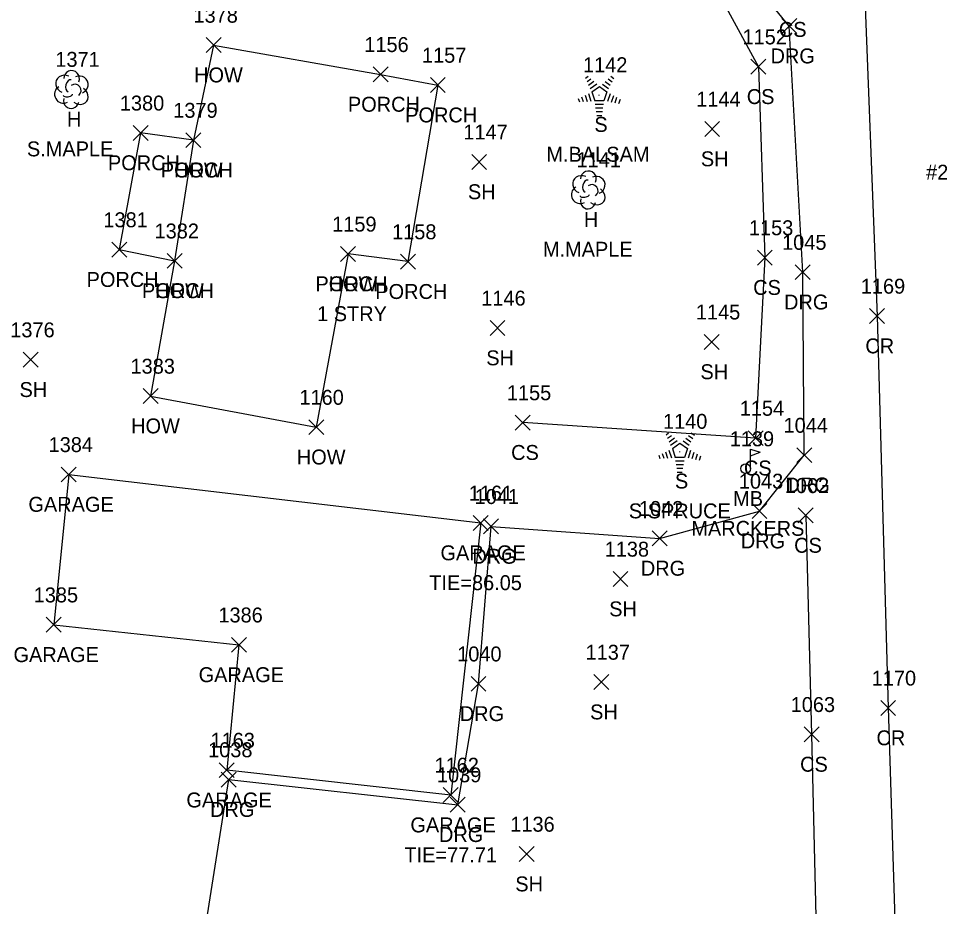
# Model space of a CAD drawing. Extents: x 1609623 to 1616187, y 756677 to 762826.
# Drawn here: x 1610505.6 to 1610629.1, y 761517.1 to 761636.1 of the extents above; entities that cross this region are included whole.
import ezdxf

# ---------------------------------------------------------------- set-up
doc = ezdxf.new("R2010")
doc.units = 0
for name, color, linetype in [('L_A', 7, 'Continuous'), ('L_C', 7, 'Continuous'), ('L_I', 7, 'Continuous'), ('L_TIC', 7, 'Continuous'), ('LBC', 7, 'Continuous'), ('LBF', 7, 'Continuous'), ('LELB', 7, 'Continuous'), ('LMB', 7, 'Continuous'), ('LTC', 7, 'Continuous'), ('LTD', 7, 'Continuous'), ('P_A', 7, 'Continuous'), ('P_I', 7, 'Continuous'), ('P_TIC', 7, 'Continuous'), ('PRC', 7, 'Continuous'), ('R_A', 7, 'Continuous'), ('R_I', 7, 'Continuous'), ('R_TIC', 7, 'Continuous'), ('RDG', 7, 'Continuous'), ('U_C', 7, 'Continuous')]:
    doc.layers.add(name, color=color, linetype=linetype)

msp = doc.modelspace()

# ---------------------------------------------------------------- linework, layer by layer
at = {"layer": 'L_TIC'}
for points in [[(1610530.77, 761631.56), (1610532.77, 761633.56)], [(1610532.77, 761631.56), (1610530.77, 761633.56)], [(1610603.8, 761628.66), (1610605.8, 761630.66)], [(1610605.8, 761628.66), (1610603.8, 761630.66)], [(1610553.15, 761627.63), (1610555.15, 761629.63)], [(1610555.15, 761627.63), (1610553.15, 761629.63)], [(1610560.83, 761626.2), (1610562.83, 761628.2)], [(1610562.83, 761626.2), (1610560.83, 761628.2)], [(1610597.6, 761620.32), (1610599.6, 761622.32)], [(1610599.6, 761620.32), (1610597.6, 761622.32)], [(1610520.98, 761619.79), (1610522.98, 761621.79)], [(1610522.98, 761619.79), (1610520.98, 761621.79)], [(1610528.06, 761618.82), (1610530.06, 761620.82)], [(1610530.06, 761618.82), (1610528.06, 761620.82)], [(1610528.06, 761618.82), (1610530.06, 761620.82)], [(1610530.06, 761618.82), (1610528.06, 761620.82)], [(1610566.37, 761615.91), (1610568.37, 761617.91)], [(1610568.37, 761615.91), (1610566.37, 761617.91)], [(1610518.12, 761604.15), (1610520.12, 761606.15)], [(1610520.12, 761604.15), (1610518.12, 761606.15)], [(1610548.79, 761603.57), (1610550.79, 761605.57)], [(1610550.79, 761603.57), (1610548.79, 761605.57)], [(1610548.79, 761603.57), (1610550.79, 761605.57)], [(1610550.79, 761603.57), (1610548.79, 761605.57)], [(1610604.66, 761603.08), (1610606.66, 761605.08)], [(1610606.66, 761603.08), (1610604.66, 761605.08)], [(1610525.54, 761602.65), (1610527.54, 761604.65)], [(1610527.54, 761602.65), (1610525.54, 761604.65)], [(1610525.54, 761602.65), (1610527.54, 761604.65)], [(1610527.54, 761602.65), (1610525.54, 761604.65)], [(1610556.82, 761602.54), (1610558.82, 761604.54)], [(1610558.82, 761602.54), (1610556.82, 761604.54)], [(1610568.83, 761593.65), (1610570.83, 761595.65)], [(1610570.83, 761593.65), (1610568.83, 761595.65)], [(1610597.54, 761591.79), (1610599.54, 761593.79)], [(1610599.54, 761591.79), (1610597.54, 761593.79)], [(1610506.26, 761589.4), (1610508.26, 761591.4)], [(1610508.26, 761589.4), (1610506.26, 761591.4)], [(1610522.32, 761584.53), (1610524.32, 761586.53)], [(1610524.32, 761584.53), (1610522.32, 761586.53)], [(1610572.21, 761580.97), (1610574.21, 761582.97)], [(1610574.21, 761580.97), (1610572.21, 761582.97)], [(1610544.53, 761580.36), (1610546.53, 761582.36)], [(1610546.53, 761580.36), (1610544.53, 761582.36)], [(1610603.42, 761578.89), (1610605.42, 761580.89)], [(1610605.42, 761578.89), (1610603.42, 761580.89)], [(1610511.34, 761574.02), (1610513.34, 761576.02)], [(1610513.34, 761574.02), (1610511.34, 761576.02)], [(1610610.15, 761568.53), (1610612.15, 761570.53)], [(1610612.15, 761568.53), (1610610.15, 761570.53)], [(1610566.58, 761567.52), (1610568.58, 761569.52)], [(1610568.58, 761567.52), (1610566.58, 761569.52)], [(1610585.31, 761560.01), (1610587.31, 761562.01)], [(1610587.31, 761560.01), (1610585.31, 761562.01)], [(1610509.34, 761553.88), (1610511.34, 761555.88)], [(1610511.34, 761553.88), (1610509.34, 761555.88)], [(1610534.16, 761551.19), (1610536.16, 761553.19)], [(1610536.16, 761551.19), (1610534.16, 761553.19)], [(1610582.75, 761546.2), (1610584.75, 761548.2)], [(1610584.75, 761546.2), (1610582.75, 761548.2)], [(1610610.94, 761539.19), (1610612.94, 761541.19)], [(1610612.94, 761539.19), (1610610.94, 761541.19)], [(1610532.52, 761534.4), (1610534.52, 761536.4)], [(1610534.52, 761534.4), (1610532.52, 761536.4)], [(1610562.55, 761531.06), (1610564.55, 761533.06)], [(1610564.55, 761531.06), (1610562.55, 761533.06)], [(1610572.72, 761523.15), (1610574.72, 761525.15)], [(1610574.72, 761523.15), (1610572.72, 761525.15)]]:
    msp.add_lwpolyline(points, dxfattribs=at)
at = {"layer": 'LBC'}
for points in [[(1610531.77, 761632.56), (1610529.06, 761619.82), (1610526.54, 761603.65), (1610523.32, 761585.53)], [(1610531.77, 761632.56), (1610554.15, 761628.63)], [(1610549.79, 761604.57), (1610545.53, 761581.36)], [(1610523.32, 761585.53), (1610545.53, 761581.36)], [(1610512.34, 761575.02), (1610510.34, 761554.88), (1610535.16, 761552.19)], [(1610512.34, 761575.02), (1610567.58, 761568.52)], [(1610567.58, 761568.52), (1610563.55, 761532.06), (1610533.52, 761535.4)], [(1610535.16, 761552.19), (1610533.52, 761535.4)]]:
    msp.add_lwpolyline(points, dxfattribs=at)
at = {"layer": 'LBF'}
for points in [[(1610554.15, 761628.63), (1610561.83, 761627.2), (1610557.82, 761603.54), (1610549.79, 761604.57)], [(1610529.06, 761619.82), (1610521.98, 761620.79), (1610519.12, 761605.15), (1610526.54, 761603.65)]]:
    msp.add_lwpolyline(points, dxfattribs=at)
at = {"layer": 'LELB'}
for points in [[(1610595.89, 761646.07), (1610604.8, 761629.66), (1610605.66, 761604.08), (1610604.42, 761579.89), (1610573.21, 761581.97)], [(1610611.15, 761569.53), (1610611.94, 761540.19), (1610612.63, 761510.1)]]:
    msp.add_lwpolyline(points, dxfattribs=at)
at = {"layer": 'LMB'}
for p, q in [((1610603.75, 761575.81), (1610603.75, 761578.41)), ((1610603.75, 761578.4), (1610605.04, 761578.02)), ((1610603.75, 761577.5), (1610605.04, 761578.01)), ((1610603.1, 761575.8), (1610603.1, 761575.8))]:
    msp.add_line(p, q, dxfattribs=at)
msp.add_circle((1610603.1, 761575.8), 0.656, dxfattribs=at)
at = {"layer": 'LTC'}
for p, q in [((1610581.62, 761628.14), (1610581.97, 761628.4)), ((1610581.83, 761627.68), (1610582.35, 761628.06)), ((1610582.03, 761627.21), (1610582.74, 761627.72)), ((1610582.24, 761626.75), (1610583.12, 761627.38)), ((1610583.9, 761627.34), (1610584.71, 761626.75)), ((1610584.27, 761627.69), (1610584.95, 761627.19)), ((1610584.64, 761628.03), (1610585.19, 761627.64)), ((1610585.01, 761628.38), (1610585.43, 761628.08)), ((1610582.01, 761626.07), (1610582.35, 761625.05)), ((1610582.47, 761626.29), (1610583.48, 761627.03)), ((1610582.47, 761626.29), (1610582.86, 761625.1)), ((1610583.48, 761627.03), (1610584.48, 761626.3)), ((1610584.48, 761626.3), (1610584.09, 761625.1)), ((1610584.92, 761626.03), (1610584.58, 761624.99)), ((1610580.65, 761625.42), (1610580.8, 761624.95)), ((1610581.1, 761625.64), (1610581.32, 761624.99)), ((1610581.56, 761625.86), (1610581.83, 761625.02)), ((1610584.09, 761625.1), (1610582.86, 761625.1)), ((1610585.36, 761625.78), (1610585.07, 761624.89)), ((1610585.8, 761625.53), (1610585.57, 761624.8)), ((1610586.25, 761625.28), (1610586.06, 761624.7)), ((1610584.05, 761624.6), (1610582.9, 761624.6)), ((1610583.96, 761624.1), (1610582.98, 761624.1)), ((1610583.88, 761623.6), (1610583.05, 761623.6)), ((1610583.8, 761623.1), (1610583.12, 761623.1)), ((1610592.42, 761580.35), (1610592.77, 761580.6)), ((1610595.81, 761580.59), (1610596.23, 761580.28)), ((1610592.63, 761579.88), (1610593.15, 761580.26)), ((1610592.84, 761579.41), (1610593.54, 761579.93)), ((1610593.04, 761578.95), (1610593.92, 761579.59)), ((1610593.27, 761578.49), (1610594.28, 761579.23)), ((1610594.28, 761579.23), (1610595.28, 761578.5)), ((1610594.7, 761579.54), (1610595.51, 761578.95)), ((1610595.07, 761579.89), (1610595.75, 761579.4)), ((1610595.44, 761580.24), (1610595.99, 761579.84)), ((1610591.9, 761577.84), (1610592.12, 761577.19)), ((1610592.36, 761578.06), (1610592.63, 761577.22)), ((1610592.81, 761578.27), (1610593.15, 761577.26)), ((1610593.27, 761578.49), (1610593.66, 761577.3)), ((1610595.28, 761578.5), (1610594.89, 761577.3)), ((1610595.72, 761578.23), (1610595.38, 761577.19)), ((1610596.16, 761577.98), (1610595.87, 761577.1)), ((1610591.45, 761577.63), (1610591.6, 761577.16)), ((1610594.89, 761577.3), (1610593.66, 761577.3)), ((1610594.85, 761576.8), (1610593.7, 761576.8)), ((1610596.6, 761577.73), (1610596.37, 761577)), ((1610597.05, 761577.48), (1610596.86, 761576.91)), ((1610594.76, 761576.3), (1610593.78, 761576.3)), ((1610594.68, 761575.8), (1610593.85, 761575.8)), ((1610594.6, 761575.3), (1610593.92, 761575.3))]:
    msp.add_line(p, q, dxfattribs=at)
at = {"layer": 'LTD'}
for p, q in [((1610512.68, 761626.65), (1610512.68, 761626.65)), ((1610512.68, 761626.65), (1610512.68, 761626.65)), ((1610581.98, 761613.2), (1610581.98, 761613.2)), ((1610581.98, 761613.2), (1610581.98, 761613.2))]:
    msp.add_line(p, q, dxfattribs=at)
for centre in [(1610512.73, 761628.09), (1610582.02, 761614.64)]:
    msp.add_arc(centre, 1.05, 335.5272, 180.9563, dxfattribs=at)
for centre, major_axis, ratio, start_param, end_param in [((1610511.89, 761627.32), (1.21, -0.51), 0.895232, 1.570796, 4.712389), ((1610513.72, 761627.24), (-1.14, -0.48), 0.949671, 1.570796, 4.712389), ((1610512.47, 761627.11), (-0.208, -0.792), 0.645439, 3.141593, 6.283185), ((1610513.18, 761626.49), (-0.5, 0.667), 0.989748, 3.141593, 6.283185), ((1610511.6, 761625.94), (0.58, -1.04), 0.959034, 3.141593, 6.283185), ((1610512.22, 761625.9), (-0.625, -0.083), 0.423636, 0, 3.141593), ((1610513.68, 761625.82), (-1.09, 0.79), 0.841452, 1.570796, 4.712389), ((1610512.68, 761625.15), (0.26, 1.06), 0.942809, 1.570796, 4.712389), ((1610581.19, 761613.87), (1.21, -0.51), 0.895232, 1.570796, 4.712389), ((1610583.02, 761613.79), (-1.14, -0.48), 0.949671, 1.570796, 4.712389), ((1610581.77, 761613.66), (-0.208, -0.792), 0.645439, 3.141593, 6.283185), ((1610582.48, 761613.04), (-0.5, 0.667), 0.989748, 3.141593, 6.283185), ((1610580.89, 761612.49), (0.58, -1.04), 0.959034, 3.141593, 6.283185), ((1610581.52, 761612.45), (-0.625, -0.083), 0.423636, 0, 3.141593), ((1610582.98, 761612.37), (-1.09, 0.79), 0.841452, 1.570796, 4.712389), ((1610581.98, 761611.7), (0.26, 1.06), 0.942809, 1.570796, 4.712389)]:
    msp.add_ellipse(centre, major_axis=major_axis, ratio=ratio, start_param=start_param, end_param=end_param, dxfattribs=at)
at = {"layer": 'P_TIC'}
for points in [[(1610619.71, 761595.25), (1610621.71, 761597.25)], [(1610621.71, 761595.25), (1610619.71, 761597.25)], [(1610621.2, 761542.73), (1610623.2, 761544.73)], [(1610623.2, 761542.73), (1610621.2, 761544.73)]]:
    msp.add_lwpolyline(points, dxfattribs=at)
at = {"layer": 'PRC'}
msp.add_lwpolyline([(1610615.34, 761821.26), (1610616.76, 761769.94), (1610617.49, 761726.01), (1610618.27, 761675.99), (1610618.81, 761645.85), (1610620.71, 761596.25), (1610622.2, 761543.73), (1610623.77, 761494.01), (1610624.8, 761445.35), (1610626.12, 761399.37), (1610627.46, 761348.43), (1610629.43, 761292.43), (1610633.7, 761219.48)], dxfattribs=at)
at = {"layer": 'R_TIC'}
for points in [[(1610607.94, 761634.11), (1610609.94, 761636.11)], [(1610609.94, 761634.11), (1610607.94, 761636.11)], [(1610609.75, 761601.13), (1610611.75, 761603.13)], [(1610611.75, 761601.13), (1610609.75, 761603.13)], [(1610609.95, 761576.61), (1610611.95, 761578.61)], [(1610611.95, 761576.61), (1610609.95, 761578.61)], [(1610603.95, 761569.12), (1610605.95, 761571.12)], [(1610605.95, 761569.12), (1610603.95, 761571.12)], [(1610567.96, 761567.06), (1610569.96, 761569.06)], [(1610569.96, 761567.06), (1610567.96, 761569.06)], [(1610590.55, 761565.46), (1610592.55, 761567.46)], [(1610592.55, 761565.46), (1610590.55, 761567.46)], [(1610566.28, 761545.97), (1610568.28, 761547.97)], [(1610568.28, 761545.97), (1610566.28, 761547.97)], [(1610532.8, 761533.13), (1610534.8, 761535.13)], [(1610534.8, 761533.13), (1610532.8, 761535.13)], [(1610563.49, 761529.77), (1610565.49, 761531.77)], [(1610565.49, 761529.77), (1610563.49, 761531.77)]]:
    msp.add_lwpolyline(points, dxfattribs=at)
at = {"layer": 'RDG'}
msp.add_lwpolyline([(1610614.38, 761469.34), (1610596.07, 761472.76), (1610561.2, 761471.9), (1610563.57, 761489.76), (1610586.13, 761490.95), (1610602.15, 761492.71), (1610613.18, 761498.39), (1610612.52, 761508.5), (1610598.82, 761507.98), (1610567.44, 761509.45), (1610530.27, 761511.75), (1610533.8, 761534.13), (1610564.49, 761530.77), (1610567.28, 761546.97), (1610568.96, 761568.06), (1610591.55, 761566.46), (1610604.95, 761570.12), (1610610.95, 761577.61), (1610610.75, 761602.13), (1610608.94, 761635.11), (1610595.07, 761652.1), (1610578.79, 761660.9)], dxfattribs=at)

# ---------------------------------------------------------------- texts
at = {"layer": 'L_A'}
for s, p in [('CS', (1610607.54, 761633.66)), ('HOW', (1610529.15, 761627.56)), ('CS', (1610603.24, 761624.66)), ('PORCH', (1610549.77, 761623.63)), ('H', (1610512.11, 761621.65)), ('PORCH', (1610557.45, 761622.2)), ('S', (1610582.81, 761620.93)), ('PORCH', (1610517.6, 761615.79)), ('SH', (1610597.09, 761616.32)), ('PORCH', (1610524.69, 761614.82)), ('HOW', (1610526.45, 761614.82)), ('SH', (1610565.86, 761611.91)), ('H', (1610581.41, 761608.2)), ('PORCH', (1610514.74, 761600.15)), ('PORCH', (1610545.42, 761599.57)), ('HOW', (1610547.18, 761599.57)), ('PORCH', (1610522.16, 761598.65)), ('HOW', (1610523.93, 761598.65)), ('PORCH', (1610553.44, 761598.54)), ('CS', (1610604.1, 761599.08)), ('SH', (1610568.32, 761589.65)), ('SH', (1610597.03, 761587.79)), ('SH', (1610505.75, 761585.4)), ('HOW', (1610520.71, 761580.53)), ('HOW', (1610542.92, 761576.36)), ('CS', (1610571.65, 761576.97)), ('CS', (1610602.86, 761574.89)), ('S', (1610593.61, 761573.14)), ('GARAGE', (1610506.94, 761570.02)), ('MB', (1610601.41, 761570.8)), ('GARAGE', (1610562.18, 761563.52)), ('CS', (1610609.59, 761564.53)), ('SH', (1610584.8, 761556.01)), ('GARAGE', (1610504.94, 761549.88)), ('GARAGE', (1610529.76, 761547.19)), ('SH', (1610582.24, 761542.2)), ('CS', (1610610.39, 761535.19)), ('GARAGE', (1610528.12, 761530.4)), ('GARAGE', (1610558.15, 761527.06)), ('SH', (1610572.21, 761519.15))]:
    msp.add_text(s, height=2, dxfattribs=at).set_placement(p)
at = {"layer": 'L_C'}
for s, p in [('S.MAPLE', (1610506.74, 761617.65)), ('M.BALSAM', (1610576.38, 761616.93)), ('M.MAPLE', (1610575.91, 761604.2)), ('1 STRY', (1610545.64, 761595.57)), ('S.SPRUCE', (1610587.43, 761569.14)), ('MARCKERS', (1610595.81, 761566.8)), ('TIE=86.05', (1610560.68, 761559.52)), ('TIE=77.71', (1610557.35, 761523.06))]:
    msp.add_text(s, height=2, dxfattribs=at).set_placement(p)
at = {"layer": 'L_I'}
for s, p in [('1378', (1610529.07, 761635.56)), ('1152', (1610602.67, 761632.66)), ('1156', (1610551.97, 761631.63)), ('1157', (1610559.7, 761630.2)), ('1371', (1610510.55, 761629.65)), ('1142', (1610581.29, 761628.93)), ('1144', (1610596.47, 761624.32)), ('1380', (1610519.2, 761623.79)), ('1379', (1610526.36, 761622.82)), ('1379', (1610526.36, 761622.82)), ('1147', (1610565.25, 761619.91)), ('1141', (1610580.42, 761616.2)), ('1381', (1610516.99, 761608.15)), ('1159', (1610547.66, 761607.57)), ('1159', (1610547.66, 761607.57)), ('1153', (1610603.53, 761607.08)), ('1382', (1610523.85, 761606.65)), ('1382', (1610523.85, 761606.65)), ('1158', (1610555.69, 761606.54)), ('1146', (1610567.65, 761597.65)), ('1145', (1610596.42, 761595.79)), ('1376', (1610504.51, 761593.4)), ('1383', (1610520.63, 761588.53)), ('1155', (1610571.08, 761584.97)), ('1160', (1610543.27, 761584.36)), ('1154', (1610602.3, 761582.89)), ('1140', (1610592.01, 761581.14)), ('1139', (1610600.96, 761578.8)), ('1384', (1610509.65, 761578.02)), ('1062', (1610608.33, 761572.53)), ('1161', (1610565.97, 761571.52)), ('1138', (1610584.19, 761564.01)), ('1385', (1610507.65, 761557.88)), ('1386', (1610532.41, 761555.19)), ('1137', (1610581.63, 761550.2)), ('1063', (1610609.13, 761543.19)), ('1163', (1610531.35, 761538.4)), ('1162', (1610561.38, 761535.06)), ('1136', (1610571.54, 761527.15))]:
    msp.add_text(s, height=2, dxfattribs=at).set_placement(p)
at = {"layer": 'LTC'}
for p in [(1610583.36, 761626.04), (1610594.16, 761578.24)]:
    msp.add_text('.', height=1.04, rotation=270, dxfattribs=at).set_placement(p)
at = {"layer": 'P_A'}
for p in [(1610619.14, 761591.25), (1610620.63, 761538.73)]:
    msp.add_text('CR', height=2, dxfattribs=at).set_placement(p)
at = {"layer": 'P_I'}
for s, p in [('1169', (1610618.53, 761599.25)), ('1170', (1610619.99, 761546.73))]:
    msp.add_text(s, height=2, dxfattribs=at).set_placement(p)
at = {"layer": 'R_A'}
for p in [(1610606.43, 761630.11), (1610608.24, 761597.13), (1610608.43, 761572.61), (1610602.44, 761565.12), (1610566.45, 761563.06), (1610589.04, 761561.46), (1610564.76, 761541.97), (1610531.29, 761529.13), (1610561.98, 761525.77)]:
    msp.add_text('DRG', height=2, dxfattribs=at).set_placement(p)
at = {"layer": 'R_I'}
for s, p in [('1045', (1610607.98, 761605.13)), ('1044', (1610608.17, 761580.61)), ('1043', (1610602.18, 761573.12)), ('1041', (1610566.76, 761571.06)), ('1042', (1610588.78, 761569.46)), ('1040', (1610564.42, 761549.97)), ('1038', (1610531.03, 761537.13)), ('1039', (1610561.71, 761533.77))]:
    msp.add_text(s, height=2, dxfattribs=at).set_placement(p)
at = {"layer": 'U_C'}
msp.add_text('#24-5/12/3', height=2, dxfattribs=at).set_placement((1610627.28, 761614.53))

doc.saveas('drawing.dxf')
